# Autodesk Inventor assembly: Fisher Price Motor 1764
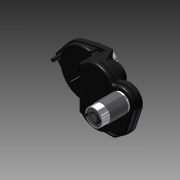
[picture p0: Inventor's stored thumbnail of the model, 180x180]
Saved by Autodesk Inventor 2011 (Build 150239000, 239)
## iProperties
Shininess: 64.0
Angle Display Precision: 2
Document Length Units: 11272
Document Angle Units: 11279
Document Time Units: 11290
Document Mass Units: 11286
Document Length Units Precision: 3
Document Angle Units Precision: 2
Category: Motors
Created: 2001-12
Document SubType Name: Assembly
Project: FIRST
Vendor: FisherPrice
Part Number: Fisher Price Motor 1764
Description: FisherPrice Motor and Gearbox
Density: 0.0
Volumn: 0.0
Area: 0.0
PropertySet Name: Model Information
Control State: 0
Master: False
Checked Out: False
Title: FisherPrice Motor and Gearbox
Author: Autodesk, Inc.
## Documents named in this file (4)
- R:\CAD Archives\Motors\Fisher Price Motor 1764\Fisher Price Motor 1764.iam
- R:\2008-2009\CAD\Kit of parts parts\All_Motors\00968-9015_Housing2.ipt
- R:\2008-2009\CAD\Kit of parts parts\All_Motors\00968-9015_Housing1.ipt
- R:\2008-2009\CAD\Kit of parts parts\All_Motors\00968-9015_Spindle.ipt
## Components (3 placed, 3 different names)
1. 00968-9015_Housing2:1 — Flush:1, Flush:2, Mate:2, Mate:3
2. 00968-9015_Housing1:1 — Flush:1, Mate:1, Mate:2, Mate:3
3. 00968-9015_Spindle:1 — Flush:2, Mate:1
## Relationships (5: Mate 3, Flush 2)
- Flush:1: 00968-9015_Housing2:1 ↔ 00968-9015_Housing1:1
- Flush:2: 00968-9015_Housing2:1 ↔ 00968-9015_Spindle:1
- Mate:1: 00968-9015_Housing1:1 ↔ 00968-9015_Spindle:1
- Mate:2: 00968-9015_Housing2:1 ↔ 00968-9015_Housing1:1
- Mate:3: 00968-9015_Housing2:1 ↔ 00968-9015_Housing1:1
